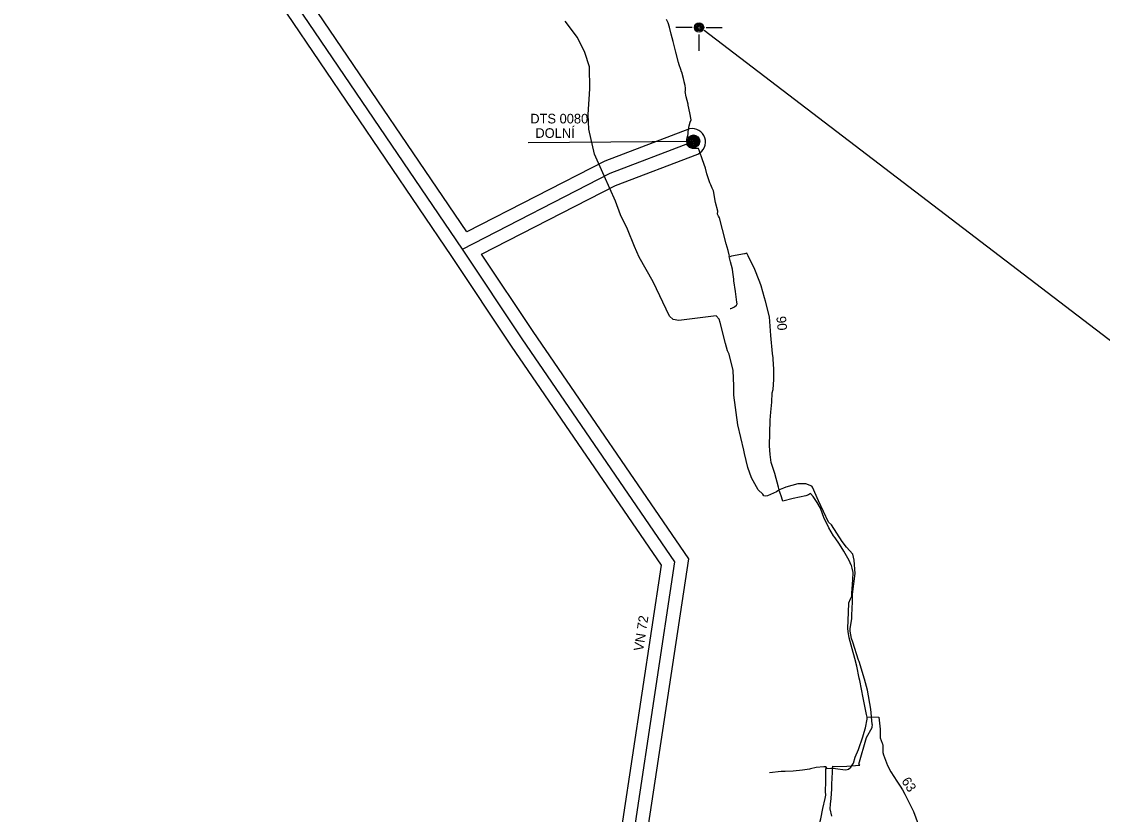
# Model space of a CAD drawing. Extents: x -545241 to -532622, y -1042837 to -1037240.
# Drawn here: x -543118 to -542219, y -1038564 to -1037905 of the extents above; entities that cross this region are included whole.
import ezdxf

# ---------------------------------------------------------------- set-up
doc = ezdxf.new("R2010")
doc.units = 0
for name, color, linetype in [('Vrstva 12', 7, 'Continuous'), ('Vrstva 16', 7, 'Continuous'), ('Vrstva 18', 7, 'Continuous'), ('Vrstva 33', 7, 'Continuous'), ('Vrstva 38', 7, 'Continuous'), ('Vrstva 58', 7, 'Continuous'), ('Vrstva 59', 7, 'Continuous'), ('Vrstva 60', 7, 'Continuous')]:
    doc.layers.add(name, color=color, linetype=linetype)

msp = doc.modelspace()

# ---------------------------------------------------------------- linework, layer by layer
at = {"layer": 'Vrstva 12'}
for radius in [5.25, 4.55, 3.85, 3.15, 2.45, 1.75, 1.05, 0.35]:
    msp.add_circle((-542559.14, -1038004.74), radius, dxfattribs=at)
at = {"layer": 'Vrstva 18'}
for points in [[(-542556.73, -1038010.64), (-542560.05, -1038010.88), (-542562.38, -1038009.81), (-542564.37, -1038007.9), (-542564.78, -1038003.33), (-542564.36, -1038001.84), (-542563.87, -1037999.93), (-542563.55, -1037998.63), (-542563.46, -1037996.77), (-542562.71, -1037991.91), (-542561.97, -1037988.99), (-542561.03, -1037986.91), (-542562.24, -1037981), (-542563.49, -1037974.71), (-542563.66, -1037973.87), (-542565.27, -1037967.73), (-542566.01, -1037963.37), (-542565.82, -1037962.73), (-542565.8, -1037960.95), (-542565.79, -1037960.48), (-542566.1, -1037958.35), (-542566.84, -1037955.36), (-542566.92, -1037955.05), (-542567.5, -1037952.69), (-542568.88, -1037947.38), (-542568.95, -1037947.13), (-542569, -1037946.93), (-542569.6, -1037945.14), (-542570.93, -1037941.17), (-542571.48, -1037939.14), (-542573.75, -1037930.67), (-542576.01, -1037921.78), (-542577.58, -1037915.6), (-542579.07, -1037909.84), (-542580.13, -1037906.38), (-542581.57, -1037903.57)], [(-542414.76, -1038483.52), (-542415.33, -1038481.33), (-542417.99, -1038467.45), (-542420.68, -1038453.08), (-542421.27, -1038451.16), (-542423.34, -1038441.05), (-542424.82, -1038434.74), (-542427.06, -1038426.81), (-542429.57, -1038417.69), (-542430.35, -1038412.4), (-542430.37, -1038412.27), (-542430.74, -1038409.79), (-542430.78, -1038409.53), (-542430.18, -1038396.65), (-542429.98, -1038388.45), (-542429.96, -1038388.41), (-542428.49, -1038385.23), (-542427.45, -1038382.99), (-542427.36, -1038380.55), (-542427.22, -1038376.98), (-542426.54, -1038369.26), (-542426.19, -1038363.19), (-542427.23, -1038359.58), (-542427.81, -1038357.56), (-542427.94, -1038357.12), (-542429.72, -1038353.24), (-542434.04, -1038345.61), (-542437.78, -1038339.74), (-542441.33, -1038334.46), (-542442.57, -1038332.69), (-542446.48, -1038326.18), (-542447.46, -1038324.19), (-542450.33, -1038318.33), (-542453.48, -1038309.87), (-542456.15, -1038305.03), (-542459.55, -1038300.06), (-542461.78, -1038297.63), (-542463.34, -1038298.63), (-542465.73, -1038299.56), (-542476.29, -1038301.78), (-542484.7, -1038303.98), (-542486.6, -1038298.62), (-542486.85, -1038298.09), (-542487.48, -1038295.77), (-542488.42, -1038292.34), (-542491.6, -1038280.86), (-542494.61, -1038271.72), (-542495.49, -1038265.04), (-542495.79, -1038258.07), (-542495.26, -1038236.72), (-542494.7, -1038229.87), (-542494.06, -1038221.58), (-542493.56, -1038213.98), (-542492.75, -1038211.07), (-542492.25, -1038202.81), (-542492.26, -1038195.56), (-542492.71, -1038188.69), (-542492.78, -1038187.41), (-542492.95, -1038184.43), (-542493.35, -1038181.47), (-542493.37, -1038181.33), (-542494.82, -1038166.18), (-542496.03, -1038150.77), (-542499.26, -1038137.66), (-542500, -1038135.03), (-542502.86, -1038124.86), (-542504.04, -1038122), (-542504.42, -1038120.58), (-542508.06, -1038111.3), (-542513.77, -1038100.09), (-542514.79, -1038097.68), (-542516.53, -1038098.21), (-542516.6, -1038098.3), (-542527.6, -1038100.38), (-542529.01, -1038100.91), (-542529.18, -1038100.42), (-542529.57, -1038099.13), (-542530.25, -1038095.65), (-542532.09, -1038089.94), (-542535.05, -1038078.15), (-542537.6, -1038068.4), (-542538.39, -1038067.07), (-542539.06, -1038065.48), (-542538.88, -1038062.96), (-542540.69, -1038055.57), (-542542.62, -1038046.06), (-542542.66, -1038045.37), (-542543.48, -1038043.67), (-542544.66, -1038040.99), (-542545.42, -1038039.39), (-542548.02, -1038031.93), (-542549.27, -1038027.23), (-542551.59, -1038020.26), (-542554.13, -1038012.96), (-542554.86, -1038010.9), (-542556.73, -1038010.64)], [(-542528.51, -1038143.78), (-542527.96, -1038143.69), (-542527.15, -1038143.55), (-542526.04, -1038142.99), (-542524.94, -1038142.44), (-542523.44, -1038140.95), (-542522.92, -1038139.85), (-542522.97, -1038138.4), (-542524.23, -1038129.79), (-542525.67, -1038120.89), (-542525.65, -1038119.01), (-542525.87, -1038117.69), (-542525.88, -1038117.6), (-542526.41, -1038113.63), (-542526.79, -1038111.1), (-542528.24, -1038105), (-542529.45, -1038100.52), (-542529.18, -1038100.42)], [(-542449.01, -1038524.76), (-542448.73, -1038524.73), (-542448.5, -1038526.15), (-542444.96, -1038525.93), (-542443.95, -1038525.89), (-542441.14, -1038526.19), (-542432.98, -1038527.22), (-542431.21, -1038527.06), (-542430.1, -1038526.86), (-542428.12, -1038525.07), (-542426.07, -1038521.74), (-542424.64, -1038516.82), (-542424.64, -1038516.81), (-542421.78, -1038510.31), (-542418.37, -1038500), (-542417.03, -1038495.94), (-542416.16, -1038492.45), (-542414.61, -1038485.29), (-542414.76, -1038483.52)], [(-542414.76, -1038483.52), (-542410.67, -1038483.34), (-542404.92, -1038483.47), (-542403.94, -1038493.59), (-542403.89, -1038497.55), (-542403.84, -1038498.14), (-542403.91, -1038498.31), (-542403.93, -1038498.69), (-542403.88, -1038500), (-542403.85, -1038500.75), (-542402.2, -1038505.23), (-542402, -1038505.69), (-542401.97, -1038505.91), (-542401.74, -1038506.45), (-542401.72, -1038507.69), (-542401.58, -1038512.92), (-542400.94, -1038514.94), (-542397.61, -1038523.67), (-542394.94, -1038528.91), (-542390.11, -1038536.8), (-542387.25, -1038540.98), (-542385.26, -1038544), (-542383.33, -1038547.63), (-542376.1, -1038561.88), (-542370.16, -1038577.77)], [(-542449.01, -1038524.76), (-542450.74, -1038524.94), (-542457.08, -1038525.5), (-542461.91, -1038526.58), (-542462.52, -1038526.72), (-542468.53, -1038527.58), (-542476.14, -1038528.31), (-542482.8, -1038528.57), (-542486.24, -1038528.66), (-542495.9, -1038529.77)], [(-542452.11, -1038590.4), (-542454, -1038586.25), (-542455.14, -1038583.71), (-542455.69, -1038581.42), (-542455.5, -1038576.17), (-542453.3, -1038568.1), (-542451.56, -1038559.45), (-542449.64, -1038551.27), (-542449.18, -1038548.47), (-542449.24, -1038545.21), (-542449.16, -1038536.9), (-542449.06, -1038530.41), (-542449.04, -1038529.24), (-542449, -1038528.01), (-542448.97, -1038526.9), (-542448.89, -1038525.58), (-542449.01, -1038524.76)]]:
    msp.add_lwpolyline(points, dxfattribs=at)
at = {"layer": 'Vrstva 33'}
for points in [[(-543118.04, -1037574.6), (-543062.53, -1037656.49), (-542897.82, -1037898.3), (-542760.49, -1038100.47), (-542710.73, -1038175.16), (-542586.13, -1038357.17), (-542618.24, -1038569.94), (-542637.1, -1038692.44), (-542649.55, -1038780.49), (-542662.8, -1038901.86), (-542687.52, -1039121.06), (-542713.53, -1039351.04)], [(-542747.73, -1038080.11), (-542871.62, -1037897.71)], [(-542562.35, -1037994.41), (-542632.86, -1038021.27), (-542747.73, -1038080.11)], [(-542735.37, -1038098.5), (-542623.9, -1038041.4), (-542555.57, -1038015.37)], [(-542626.19, -1038772.45), (-542615.33, -1038695.65), (-542596.49, -1038573.25), (-542563.09, -1038351.89), (-542692.5, -1038162.85), (-542735.37, -1038098.5)]]:
    msp.add_lwpolyline(points, dxfattribs=at)
msp.add_arc((-542560.27, -1038005.32), 11.1, 295.04351, 100.80102, dxfattribs=at)
at = {"layer": 'Vrstva 38'}
for points in [[(-542685.39, -1040094.76), (-542785.51, -1039938.3), (-542776.4, -1039862.98), (-542765.17, -1039797.61), (-542729.74, -1039558.36), (-542713.51, -1039451.04), (-542703.82, -1039363.05), (-542676.58, -1039122.3), (-542651.86, -1038903.07), (-542638.63, -1038781.86), (-542626.22, -1038694.04), (-542607.37, -1038571.6), (-542574.61, -1038354.53), (-542701.61, -1038169.01), (-542751.37, -1038094.33), (-542888.72, -1037892.11), (-543053.43, -1037650.31), (-543107.91, -1037569.92)], [(-542751.37, -1038094.33), (-542628.38, -1038031.33), (-542561.59, -1038005.9)]]:
    msp.add_lwpolyline(points, dxfattribs=at)
at = {"layer": 'Vrstva 58'}
for points in [[(-542410.62, -1038492.09), (-542410.56, -1038491.42), (-542410.3, -1038490.26), (-542410.56, -1038489.45), (-542411.51, -1038477), (-542414.49, -1038461.11), (-542416.75, -1038451.84), (-542421.27, -1038437.34), (-542421.88, -1038436.05), (-542426.58, -1038421.15), (-542427.59, -1038418.07), (-542428.68, -1038412.07), (-542428.77, -1038410.56), (-542428.84, -1038409.79), (-542427.38, -1038401.73), (-542427.29, -1038398.84), (-542426.91, -1038387.75), (-542426.98, -1038385.7), (-542426.91, -1038381.35), (-542424.73, -1038363.96), (-542425.61, -1038353.02), (-542426.72, -1038347.89), (-542431.94, -1038342.23), (-542435.49, -1038337.45), (-542444.25, -1038323.56), (-542446.84, -1038321.51), (-542455.15, -1038303.65), (-542460.04, -1038292.3), (-542460.73, -1038291.43), (-542465.65, -1038289.44), (-542472.35, -1038289.67), (-542482.38, -1038292.36), (-542484.28, -1038293.07), (-542488.4, -1038294.72), (-542489.01, -1038295.41), (-542490.08, -1038296.2), (-542497.63, -1038299.45), (-542499.38, -1038299.81), (-542500.7, -1038299.66), (-542501.39, -1038298.24), (-542505.31, -1038294.54), (-542510.85, -1038284.58), (-542513.99, -1038276.04), (-542516.7, -1038264.42), (-542517.23, -1038261.57), (-542519.88, -1038251.14), (-542522.16, -1038240.38), (-542525.45, -1038215.91), (-542525.55, -1038208.09), (-542526.05, -1038195.46), (-542529.55, -1038181.87), (-542530.81, -1038179.05), (-542532.58, -1038172.77), (-542536.89, -1038155.31), (-542537.9, -1038152.52), (-542540.37, -1038149.96), (-542571.34, -1038153.75), (-542575.94, -1038152.84), (-542579.17, -1038150.06), (-542592.57, -1038121.63), (-542604.27, -1038101.08), (-542608.18, -1038092.34), (-542614.07, -1038077.89), (-542619.91, -1038066.04), (-542624.13, -1038054.67), (-542633.41, -1038033.46), (-542641.36, -1038015.51), (-542646.24, -1037994.67), (-542646.73, -1037982.38), (-542645.28, -1037961.22), (-542645.71, -1037942.92), (-542649.48, -1037930.83), (-542655.71, -1037918.4), (-542665.89, -1037904.97)], [(-542444.19, -1038565.81), (-542445.51, -1038559.64), (-542445.21, -1038555.84), (-542444.73, -1038551.02), (-542444.08, -1038543.24), (-542443.99, -1038539.18), (-542443.11, -1038524.29), (-542441.47, -1038524.41), (-542431.63, -1038524.26), (-542420.85, -1038523.36), (-542421.58, -1038522.57), (-542415.34, -1038500.37), (-542410.62, -1038492.09)]]:
    msp.add_lwpolyline(points, dxfattribs=at)
at = {"layer": 'Vrstva 59'}
msp.add_line((-542696.71, -1038005.81), (-542559.14, -1038004.74), dxfattribs=at)
msp.add_lwpolyline([(-540237.69, -1039677.88), (-540249.87, -1039668.59), (-541016.65, -1039083.33), (-541783.44, -1038498.07), (-542550.23, -1037912.81)], dxfattribs=at)
at = {"layer": 'Vrstva 60'}
for points in [[(-542560.33, -1037910.14), (-542573.89, -1037910.14)], [(-542548.72, -1037910.14), (-542535.17, -1037910.14)], [(-542554.53, -1037929.5), (-542554.53, -1037915.95)]]:
    msp.add_lwpolyline(points, dxfattribs=at)
for radius in [3.87, 2.9, 1.94, 0.968]:
    msp.add_circle((-542554.53, -1037910.14), radius, dxfattribs=at)

# ---------------------------------------------------------------- texts
at = {"layer": 'Vrstva 16'}
for s, rotation, p in [('90', 275.4671, (-542490.26, -1038150.53)), ('63', 303.3825, (-542386.49, -1038536.68))]:
    msp.add_text(s, height=8, rotation=rotation, dxfattribs=at).set_placement(p)
at = {"layer": 'Vrstva 59'}
for s, p in [('DTS 0080', (-542694.89, -1037989.94)), ('DOLNÍ', (-542690.65, -1038001.94))]:
    msp.add_text(s, height=8, dxfattribs=at).set_placement(p)
msp.add_text('VN 72', height=8, rotation=81.23963, dxfattribs=at).set_placement((-542601.06, -1038429.08))

doc.saveas('drawing.dxf')
